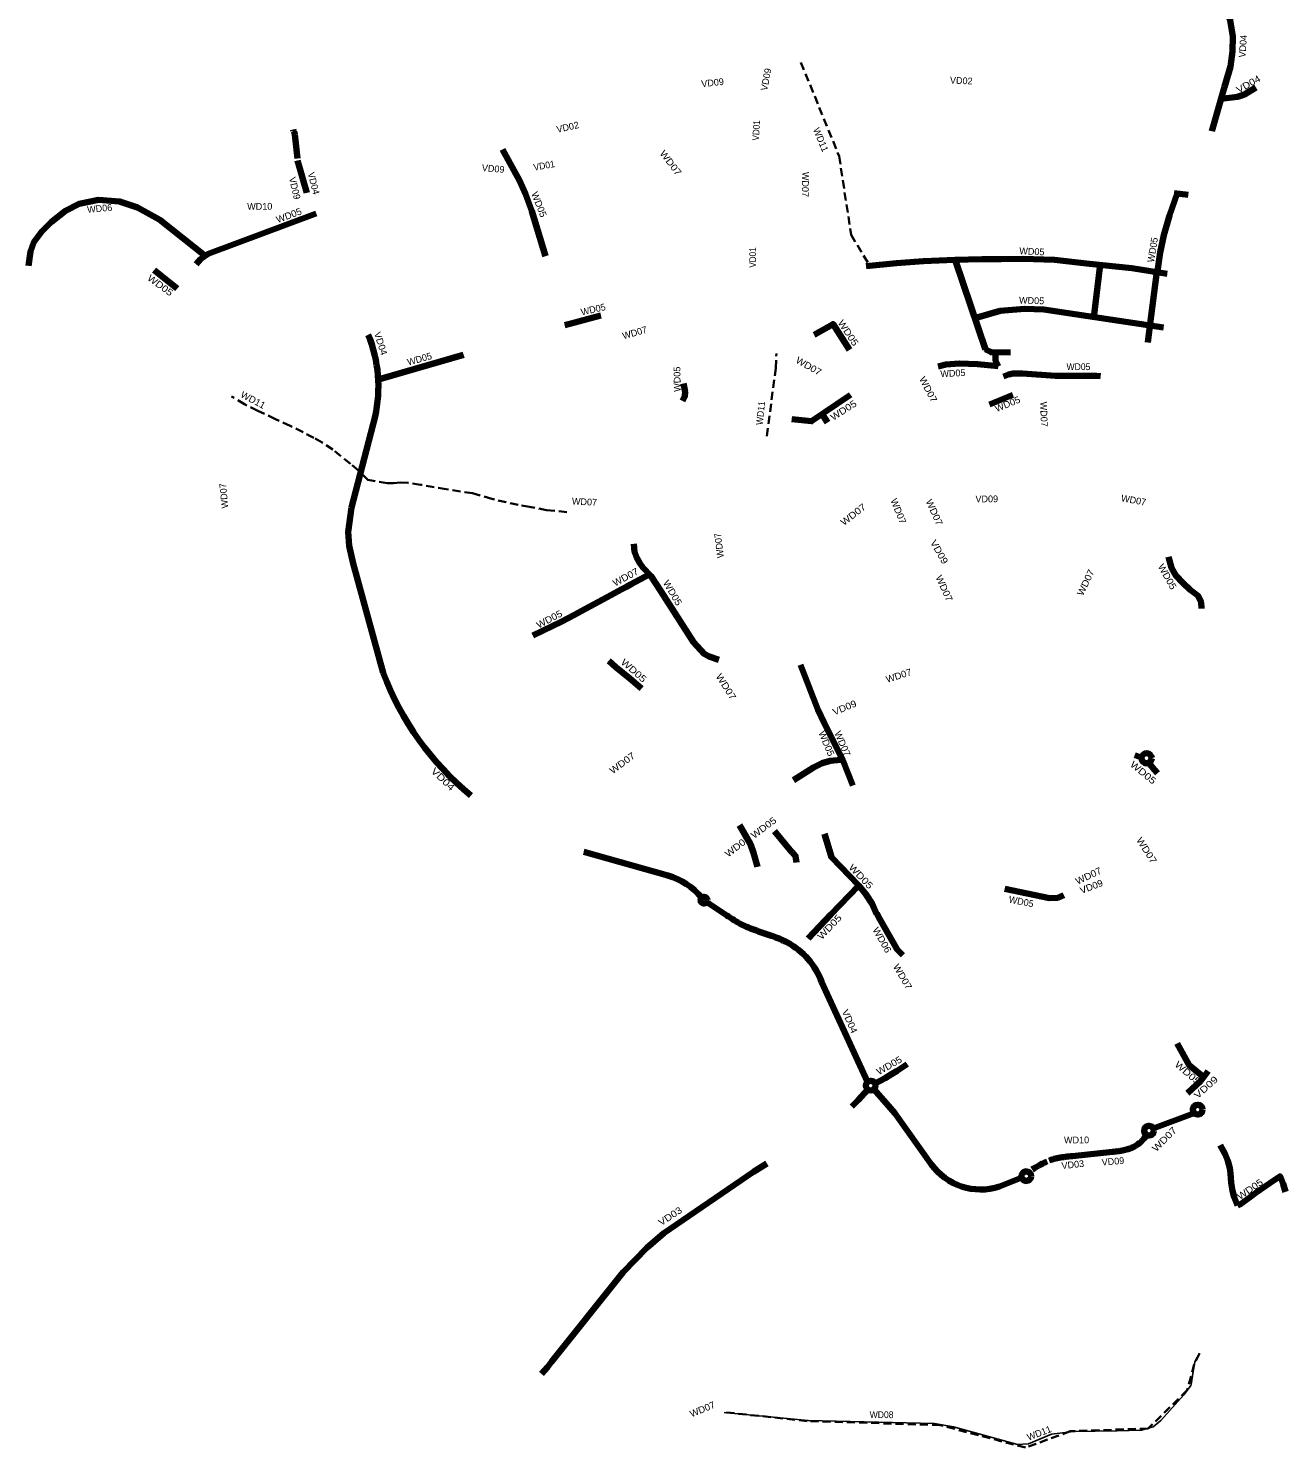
# Model space of a CAD drawing. Extents: x -650082 to -644047, y -1073232 to -1066669.
# Drawn here: x -650082 to -646363, y -1073058 to -1068858 of the extents above; entities that cross this region are included whole.
import ezdxf

# ---------------------------------------------------------------- set-up
doc = ezdxf.new("R2010")
doc.units = 0
doc.header["$LTSCALE"] = 8
doc.linetypes.add('MEDIUM_DASHED', pattern=[4.5, 3, -1.5])
for name, color, linetype in [('1', 7, 'Continuous'), ('10', 7, 'Continuous'), ('14', 7, 'Continuous'), ('2', 7, 'Continuous'), ('3', 7, 'Continuous'), ('4', 7, 'Continuous'), ('5', 7, 'Continuous'), ('6', 7, 'Continuous'), ('7', 7, 'Continuous'), ('9', 7, 'Continuous')]:
    doc.layers.add(name, color=color, linetype=linetype)
for name, color, linetype, lineweight in [('11', 7, 'Continuous', 106), ('12', 7, 'Continuous', 106), ('13', 7, 'MEDIUM_DASHED', 35), ('47', 7, 'Continuous', 106), ('51', 7, 'Continuous', 106), ('8', 7, 'Continuous', 25)]:
    doc.layers.add(name, color=color, linetype=linetype, lineweight=lineweight)

msp = doc.modelspace()

# ---------------------------------------------------------------- linework, layer by layer
at = {"layer": '11'}
for p, q in [((-649286.296, -1069243.402), (-649294.037, -1069172.192)), ((-649258.547, -1069344.39), (-649285.681, -1069249.06)), ((-649126.823, -1070275.677), (-649056.809, -1070006.786)), ((-648190.636, -1071365.392), (-648439.544, -1071295.299)), ((-647735.858, -1071680.067), (-647599.793, -1071975.634))]:
    msp.add_line(p, q, dxfattribs=at)
for points in [[(-646581.274, -1069162.086), (-646543.734, -1069031.454), (-646526.307, -1068970.81), (-646520.034, -1068926.895), (-646519.124, -1068882.525), (-646527.13, -1068833.717), (-646541.089, -1068803.463), (-646555.823, -1068777.863), (-646576.76, -1068753.039), (-646603.929, -1068734.295), (-646632.204, -1068718.474)], [(-646553.797, -1069066.473), (-646505.955, -1069060.333), (-646484.805, -1069053.474), (-646451.286, -1069033.122)], [(-649126.823, -1070275.677), (-649136.116, -1070347.82), (-649133.06, -1070389.586), (-649121.855, -1070441.538), (-649032.534, -1070765.134)], [(-648075.374, -1071443.872), (-648022.004, -1071479.581), (-648016.461, -1071483.285), (-648010.907, -1071486.974), (-648005.332, -1071490.629), (-647999.724, -1071494.234), (-647994.074, -1071497.773), (-647988.372, -1071501.227), (-647982.61, -1071504.58), (-647976.78, -1071507.812), (-647970.874, -1071510.906), (-647963.887, -1071513.957), (-647958.108, -1071516.621), (-647952.275, -1071519.164), (-647946.395, -1071521.599), (-647940.477, -1071523.938), (-647934.527, -1071526.195), (-647928.551, -1071528.382), (-647922.556, -1071530.515), (-647916.545, -1071532.605), (-647910.525, -1071534.668), (-647904.5, -1071536.717), (-647895.595, -1071539.745), (-647889.576, -1071541.81), (-647883.568, -1071543.908), (-647877.578, -1071546.054), (-647871.61, -1071548.265), (-647865.673, -1071550.555), (-647859.774, -1071552.942), (-647853.921, -1071555.438), (-647848.123, -1071558.061), (-647842.39, -1071560.823), (-647836.733, -1071563.738)]]:
    msp.add_lwpolyline(points, dxfattribs=at)
msp.add_circle((-648083.781, -1071438.172), 10.157, dxfattribs=at)
for centre, radius, start, end in [((-649390.897, -1069197.054), 100, 14.39558, 23.46117), ((-649452.625, -1069917.995), 405.652, 347.35635, 22.18649), ((-648232.695, -1070467.567), 853.398, 200.40686, 230.69896), ((-648244.965, -1071557.871), 200, 39.49461, 74.23772), ((-647937.958, -1071753.418), 215, 19.9479, 61.91292)]:
    msp.add_arc(centre, radius, start, end, dxfattribs=at)
at = {"layer": '12'}
for p, q in [((-646754.674, -1072114.023), (-646633.694, -1072068.165)), ((-646993.404, -1072195.535), (-646875.615, -1072182.532)), ((-647145.028, -1072259.442), (-647209.69, -1072285.315))]:
    msp.add_line(p, q, dxfattribs=at)
for points in [[(-647646.641, -1072049.031), (-647627.876, -1072030.328), (-647598.733, -1071998.754)], [(-647581.398, -1071997.866), (-647544.374, -1072039.387), (-647519.615, -1072068.332), (-647409.551, -1072222.875)], [(-647062.642, -1072208.565), (-647057.907, -1072206.959), (-647053.125, -1072205.5), (-647048.303, -1072204.179), (-647043.448, -1072202.984), (-647038.565, -1072201.905), (-647033.661, -1072200.931), (-647028.739, -1072200.051), (-647023.804, -1072199.253), (-647018.857, -1072198.525), (-647013.902, -1072197.856), (-647008.941, -1072197.235), (-647003.975, -1072196.649), (-646999.007, -1072196.086), (-646994.037, -1072195.536)], [(-646876.248, -1072183.165), (-646872.383, -1072182.737), (-646868.519, -1072182.3), (-646864.657, -1072181.844), (-646860.798, -1072181.36), (-646856.944, -1072180.839), (-646853.097, -1072180.272), (-646849.258, -1072179.649), (-646845.43, -1072178.963), (-646841.617, -1072178.202), (-646837.82, -1072177.36), (-646834.045, -1072176.427), (-646830.296, -1072175.394), (-646826.578, -1072174.254), (-646822.898, -1072172.998), (-646819.262, -1072171.619), (-646815.677, -1072170.111), (-646812.154, -1072168.466), (-646808.701, -1072166.678)], [(-647897.477, -1072217.517), (-647936.91, -1072242.12), (-648202.059, -1072423.781), (-648253.06, -1072467.272), (-648322.321, -1072539.514), (-648534.375, -1072804.118), (-648546.627, -1072820.111), (-648563.924, -1072839.863)], [(-647112.659, -1072235.417), (-647108.405, -1072232.79), (-647104.143, -1072230.176), (-647099.863, -1072227.591), (-647095.557, -1072225.05), (-647091.218, -1072222.565), (-647086.838, -1072220.154), (-647082.411, -1072217.83), (-647077.93, -1072215.611), (-647073.393, -1072213.512), (-647068.794, -1072211.549)]]:
    msp.add_lwpolyline(points, dxfattribs=at)
for centre in [(-647590.655, -1071986.8), (-646623.358, -1072058.099), (-646767.624, -1072120.384), (-647130.12, -1072255.012)]:
    msp.add_circle(centre, 14.428, dxfattribs=at)
for centre, radius, start, end in [((-646851.756, -1072087.012), 90, 298.5808, 324.78461), ((-647266.212, -1072116.452), 178.071, 215.23547, 288.50636)]:
    msp.add_arc(centre, radius, start, end, dxfattribs=at)
at = {"layer": '13'}
for points in [[(-647796.971, -1068958.769), (-647683.968, -1069236.597), (-647648.396, -1069468.745), (-647594.062, -1069560.317), (-647340.265, -1069541.717), (-647253.655, -1069810.08), (-647231.91, -1069823.971)], [(-647897.53, -1070064.61), (-647871.671, -1069864.156), (-647869.45, -1069820.63)], [(-648489.42, -1070289.79), (-648549.11, -1070283.64), (-648599.41, -1070274.03), (-648633.75, -1070268.38), (-648711.24, -1070250.44), (-648768.32, -1070233.86), (-648846.76, -1070222.17), (-648921.87, -1070208.67), (-648959.67, -1070203.09), (-648981.35, -1070202.4), (-649002.23, -1070203.94), (-649021.05, -1070203.56), (-649078.099, -1070194.501), (-649106.06, -1070166.8), (-649129.57, -1070146.73), (-649181.7, -1070104.45), (-649213.21, -1070083.53), (-649237.78, -1070069.79), (-649307.84, -1070034.18), (-649351.66, -1070014.26), (-649403.65, -1069989.85), (-649442.47, -1069970.36), (-649481, -1069947.32)], [(-646618.098, -1072779.957), (-646633.878, -1072812.319), (-646654.064, -1072888.773), (-646770.097, -1073001.842), (-647000.119, -1073009.906), (-647132.968, -1073058.363), (-647385.213, -1072991.734), (-647778.715, -1072979.619), (-648025.915, -1072953.371)]]:
    msp.add_lwpolyline(points, dxfattribs=at)
at = {"layer": '47'}
for p, q in [((-646692.985, -1069346.026), (-646651.217, -1069350.274)), ((-647339.967, -1069545.744), (-647251.088, -1069808.426)), ((-649642.332, -1069628.173), (-649710.271, -1069574.044)), ((-646912.03, -1069558.076), (-646930.389, -1069712.594)), ((-648494.915, -1069736.521), (-648388.804, -1069707.486)), ((-647207.164, -1069694.062), (-647282.295, -1069716.194)), ((-649043.757, -1069896.46), (-648795.401, -1069824.199)), ((-647170.402, -1069942.221), (-647239.362, -1069971.673)), ((-647718.115, -1070024.038), (-647733.777, -1069999.441)), ((-647672.743, -1071023.641), (-647643.873, -1071098.745)), ((-646808.839, -1071008.864), (-646795.926, -1071014.301)), ((-647824.318, -1071296.38), (-647875.239, -1071233.632)), ((-647708.122, -1071480.45), (-647626.882, -1071395.872)), ((-647708.122, -1071480.45), (-647775.697, -1071551.243))]:
    msp.add_line(p, q, dxfattribs=at)
for points in [[(-648552.408, -1069532.362), (-648592.697, -1069398.642), (-648611.424, -1069347.704), (-648629.402, -1069308.002), (-648679.548, -1069216.178)], [(-646742.322, -1069576.725), (-646734.087, -1069520.908), (-646723.107, -1069469.667), (-646706.636, -1069412.02), (-646684.285, -1069346.911)], [(-649586.177, -1069556.212), (-649573.053, -1069541.298), (-649550.047, -1069525.713), (-649230.786, -1069405.644)], [(-647603.51, -1069561.425), (-647514.414, -1069553.281), (-647434.342, -1069547.122), (-647341.331, -1069542.596), (-647262.07, -1069540.647), (-647204.248, -1069540.647), (-647140.134, -1069540.07), (-647047.049, -1069543.256), (-646943.2, -1069554.795), (-646817.923, -1069567.982), (-646714.075, -1069584.466)], [(-646744.044, -1069579.015), (-646764.641, -1069739.238), (-646770.927, -1069787.596)], [(-646724.352, -1069743.581), (-647078.839, -1069690.268), (-647135.789, -1069688.123), (-647207.164, -1069694.062)], [(-647757.476, -1069764.575), (-647701.982, -1069733.103), (-647653.087, -1069809.089)], [(-647390.821, -1069859.073), (-647368.021, -1069852.558), (-647328.004, -1069849.767), (-647274.492, -1069852.093), (-647213.899, -1069857.686)], [(-647251.088, -1069808.426), (-647232.613, -1069816.264), (-647177.241, -1069817.194)], [(-647213.795, -1069859.205), (-647220.933, -1069841.605), (-647221.408, -1069819.284)], [(-647197.567, -1069888.373), (-647182.853, -1069882.067), (-647168.927, -1069879.439), (-647141.6, -1069879.965), (-647044.065, -1069885.918), (-646922.882, -1069885.918), (-646911.17, -1069886.938)], [(-648147.091, -1069960.576), (-648140.266, -1069946.926), (-648139.508, -1069934.035), (-648144.058, -1069909.01)], [(-647650.097, -1069942.883), (-647765.549, -1070020.915), (-647823.598, -1070014.961)], [(-648290.966, -1070383.374), (-648288.845, -1070406.899), (-648282.079, -1070425.044), (-648273.16, -1070440.728), (-648264.17, -1070453.236), (-648241.202, -1070478.118), (-648211.195, -1070523.918)], [(-646709.343, -1070422.319), (-646700.372, -1070454.216), (-646687.863, -1070477.44), (-646666.258, -1070500.316), (-646645.289, -1070519.379), (-646621.777, -1070537.807), (-646613.517, -1070556.235), (-646612.246, -1070574.663)], [(-648589.664, -1070655.082), (-648504.268, -1070613.585), (-648469.046, -1070594.986), (-648434.122, -1070576.22), (-648370.201, -1070541.371), (-648326.641, -1070517.498), (-648313.175, -1070510.435), (-648300.652, -1070503.633), (-648244.358, -1070473.301)], [(-648039.532, -1070726.638), (-648068.169, -1070717.378), (-648082.709, -1070709.44), (-648115.092, -1070674.163), (-648211.195, -1070523.918)], [(-648268.369, -1070811.262), (-648303.087, -1070781.942), (-648344.753, -1070748.129), (-648364.772, -1070729.983)], [(-647798.303, -1070741.695), (-647747.4, -1070874.36), (-647727.829, -1070913.158), (-647672.743, -1071023.641)], [(-647677.55, -1071022.921), (-647710.774, -1071025.971), (-647733.735, -1071032.504), (-647759.543, -1071045.17), (-647818.707, -1071082.607)], [(-646741.751, -1071062.202), (-646751.573, -1071052.898), (-646766.082, -1071034.526)], [(-647925.368, -1071339.891), (-647936.852, -1071298.253), (-647946.561, -1071272.093), (-647978.731, -1071216.254)], [(-647727.338, -1071242.207), (-647706.62, -1071310.667), (-647625.213, -1071395.211), (-647604.958, -1071420.095), (-647586.504, -1071448.747), (-647573.087, -1071478.317)], [(-647810.393, -1071327.127), (-647812.572, -1071307.894), (-647823.337, -1071295.659)], [(-647193.49, -1071404.445), (-647061.509, -1071431.827), (-647037.352, -1071430.861), (-647019.146, -1071423.327)], [(-646684.409, -1071862), (-646648.676, -1071926.01), (-646609.296, -1071959.529)], [(-647577.687, -1071980.477), (-647548.027, -1071965.02), (-647528.6, -1071953.175), (-647512.49, -1071943.224), (-647482.989, -1071923.852)], [(-646592.707, -1071943.76), (-646614.335, -1071972.381), (-646653.429, -1072008.981)], [(-646556.924, -1072163.008), (-646541.975, -1072190.142), (-646534.08, -1072209.348), (-646528.451, -1072231.169), (-646526.022, -1072245.895), (-646524.078, -1072274.419), (-646520.515, -1072298.567), (-646515.575, -1072317.043), (-646505.446, -1072341.949)], [(-646505.446, -1072341.949), (-646496.463, -1072338.193), (-646468.402, -1072317.124), (-646451.071, -1072304.158), (-646409.932, -1072275.634), (-646379.686, -1072255.456), (-646370.251, -1072277.255), (-646363.282, -1072301.269)]]:
    msp.add_lwpolyline(points, dxfattribs=at)
msp.add_circle((-646774.452, -1071018.284), 15.055, dxfattribs=at)
at = {"layer": '51'}
for points in [[(-649558.921, -1069531.725), (-649693.075, -1069424.839), (-649759.229, -1069388.516), (-649812.457, -1069370.063), (-649874.912, -1069365.805), (-649931.689, -1069377.161), (-649972.852, -1069398.452), (-650014.541, -1069431.96), (-650043.673, -1069460), (-650065.774, -1069491.142), (-650076.339, -1069518.627), (-650082.165, -1069560.934)], [(-647572.568, -1071477.763), (-647563.965, -1071494.251), (-647512.351, -1071583.86), (-647495.989, -1071600.795)]]:
    msp.add_lwpolyline(points, dxfattribs=at)
at = {"layer": '8'}
for points in [[(-646641.615, -1072861.847), (-646642.788, -1072871.592), (-646636.323, -1072833.305), (-646631.944, -1072804.277), (-646618.055, -1072778.52)], [(-648023.648, -1072953.961), (-647775.451, -1072978.577), (-647402.33, -1072986.644), (-647345.858, -1072996.728), (-647156.272, -1073049.167), (-647124.002, -1073047.15), (-647055.429, -1073018.914), (-646990.889, -1073010.846), (-646861.81, -1073008.83), (-646789.202, -1073006.813), (-646754.915, -1072996.728), (-646732.73, -1072978.577), (-646664.156, -1072901.935), (-646642.762, -1072873.366)]]:
    msp.add_lwpolyline(points, dxfattribs=at)

# ---------------------------------------------------------------- texts
at = {"layer": '1'}
for rotation, width, p in [(86.772, 0.9, (-647921.103, -1069190.627)), (9.97, 0.95, (-648586.178, -1069279.341)), (90.083, 0.9, (-647929.691, -1069566.304))]:
    msp.add_text('VD01', height=20, rotation=rotation, dxfattribs=dict(at, width=width)).set_placement(p)
at = {"layer": '10'}
for p in [(-649434.865, -1069395.02), (-647018.705, -1072158.017)]:
    msp.add_text('WD10', height=20, rotation=0.318, dxfattribs=at).set_placement(p)
at = {"layer": '14'}
for rotation, p in [(292.311, (-647761.508, -1069157.121)), (20.83, (-647123.491, -1073037.925))]:
    msp.add_text('WD11', height=20, rotation=rotation, dxfattribs=at).set_placement(p)
for rotation, width, p in [(332.078, 1.05, (-649456.64, -1069948.265)), (83.81, 0.95, (-647910.311, -1070032.951))]:
    msp.add_text('WD11', height=20, rotation=rotation, dxfattribs=dict(at, width=width)).set_placement(p)
at = {"layer": '2'}
for rotation, p in [(357.375, (-647356.457, -1069021.082)), (12.542, (-648517.473, -1069167.221))]:
    msp.add_text('VD02', height=20, rotation=rotation, dxfattribs=at).set_placement(p)
at = {"layer": '3'}
msp.add_text('VD03', height=20, rotation=6.009, dxfattribs=at).set_placement((-647025.037, -1072234.169))
at = {"layer": '3', "width": 1.15}
msp.add_text('VD03', height=20, rotation=33.391, dxfattribs=at).set_placement((-648210.42, -1072403.064))
at = {"layer": '4'}
for rotation, p in [(85.893, (-646482.108, -1068944.939)), (284.235, (-649256.065, -1069286.662))]:
    msp.add_text('VD04', height=20, rotation=rotation, dxfattribs=at).set_placement(p)
for rotation, width, p in [(29.411, 1.15, (-646502.014, -1069050.708)), (287.6, 1.05, (-649060.021, -1069760.208)), (316.159, 1.25, (-648893.138, -1071058.344)), (293.494, 1.1, (-647676.428, -1071767.021))]:
    msp.add_text('VD04', height=20, rotation=rotation, dxfattribs=dict(at, width=width)).set_placement(p)
at = {"layer": '5'}
for rotation, width, p in [(291.57, 1.05, (-648595.322, -1069346.682)), (20.413, 1.05, (-649344.656, -1069434.505)), (323.794, 1.15, (-649732.394, -1069601.306)), (303.586, 1.15, (-647689.055, -1069729.375)), (359.771, 0.95, (-647011.407, -1069869.205)), (32.763, 1.15, (-647701.559, -1070019.86)), (22.562, 1.05, (-647217.993, -1069994.051)), (299.409, 1.1, (-646742.052, -1070450.235)), (300.371, 1.1, (-648205.967, -1070498.405)), (27.93, 1.1, (-648572.628, -1070634.584)), (318.812, 1.2, (-648331.556, -1070736.821)), (292.87, 1.05, (-647745.74, -1070942.497)), (320.604, 1.2, (-646825.309, -1071040.045)), (36.91, 1.15, (-647935.396, -1071257.441)), (313.863, 1.2, (-647657.525, -1071342.864)), (46.414, 1.2, (-647735.69, -1071556.53)), (29.944, 1.1, (-647566.364, -1071956.55)), (319.129, 1.2, (-646693.266, -1071927.68)), (34.487, 1.15, (-646498.118, -1072326.083))]:
    msp.add_text('WD05', height=20, rotation=rotation, dxfattribs=dict(at, width=width)).set_placement(p)
for rotation, p in [(357.197, (-647151.356, -1069526.302)), (80.615, (-646752.852, -1069551.846)), (12.814, (-648445.492, -1069707.786)), (358.177, (-647151.994, -1069672.198)), (15.559, (-648958.337, -1069856.049)), (90.808, (-648152.699, -1069933.435)), (2.857, (-647383.984, -1069890.409)), (348.607, (-647183.65, -1071444.769))]:
    msp.add_text('WD05', height=20, rotation=rotation, dxfattribs=at).set_placement(p)
at = {"layer": '6'}
msp.add_text('WD06', height=20, rotation=5.442, dxfattribs=at).set_placement((-649907.373, -1069404.507))
at = {"layer": '6', "width": 1.1}
msp.add_text('WD06', height=20, rotation=299.586, dxfattribs=at).set_placement((-647586.001, -1071525.44))
at = {"layer": '7'}
for rotation, width, p in [(307.201, 1.15, (-648216.084, -1069228.211)), (330.302, 1.1, (-647814.4, -1069846.044)), (297.667, 1.1, (-647448.246, -1069895.109)), (37.889, 1.15, (-647669.893, -1070330.992)), (292.116, 1.05, (-647532.629, -1070254.406)), (294.454, 1.1, (-647428.465, -1070257.434)), (28.414, 1.1, (-648346.892, -1070510.452)), (294.454, 1.1, (-647399.207, -1070482.213)), (64.535, 1.1, (-646963.014, -1070539.33)), (302.302, 1.15, (-648049.847, -1070775.71)), (17.803, 1.05, (-647541.835, -1070795.135)), (293.26, 1.05, (-647698.608, -1070943.099)), (36.212, 1.15, (-648354.157, -1071065.604)), (37.876, 1.15, (-648012.3, -1071312.413)), (302.643, 1.15, (-646805.959, -1071260.156)), (25.46, 1.1, (-646978.911, -1071392.769)), (299.885, 1.1, (-647525.38, -1071634.155)), (45.026, 1.2, (-646746.182, -1072184.521)), (22.432, 1.05, (-648120.604, -1072968.926))]:
    msp.add_text('WD07', height=20, rotation=rotation, dxfattribs=dict(at, width=width)).set_placement(p)
for rotation, p in [(269.034, (-647793.034, -1069282.646)), (16.02, (-648321.58, -1069778.479)), (272.013, (-647089.498, -1069963.268)), (95.41, (-649490.694, -1070277.596)), (357.034, (-648474.765, -1070267.044)), (349.845, (-646850.986, -1070257.62)), (97.026, (-648024.784, -1070424.219))]:
    msp.add_text('WD07', height=20, rotation=rotation, dxfattribs=at).set_placement(p)
at = {"layer": '8', "width": 0.95}
msp.add_text('WD08', height=20, rotation=359.822, dxfattribs=at).set_placement((-647593.734, -1072970.888))
at = {"layer": '9'}
for rotation, p in [(6.253, (-648090.523, -1069032.33)), (78.961, (-647896.883, -1069044.007)), (355.112, (-648741.445, -1069280.24)), (283.42, (-649311.686, -1069300.906)), (0.216, (-647280.667, -1070260.641)), (4.69, (-646906.544, -1072223.962))]:
    msp.add_text('VD09', height=20, rotation=rotation, dxfattribs=at).set_placement(p)
for rotation, width, p in [(299.658, 1.15, (-647415.603, -1070379.066)), (22.494, 1.1, (-647698.244, -1070891.729)), (20.79, 1.05, (-646967.13, -1071419.926)), (41.768, 1.25, (-646623.484, -1072027.315))]:
    msp.add_text('VD09', height=20, rotation=rotation, dxfattribs=dict(at, width=width)).set_placement(p)

doc.saveas('drawing.dxf')
